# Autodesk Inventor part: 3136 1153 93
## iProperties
Shininess: 20.0
Length Units: 11269
Angle Units: 11279
Time Units: 11290
Mass Units: 11283
Length Display Precision: 3
Angle Display Precision: 2
Compacted: True
Created: 2000-11
Part Number: 3136 1153 93
Material: Steel, Mild
Document SubType Name: Modeling
Designer: Joe M
Engineer: Joe M
Density: 0.0
Volumn: 0.0
Area: 0.0
PropertySet Name: Model Information
Control State: 0
Master: False
Checked Out: False
Last Check In By: brjdn
Last Check In Date: 2001-03-05
Title: Sidoanslutning
Author: Joe M
